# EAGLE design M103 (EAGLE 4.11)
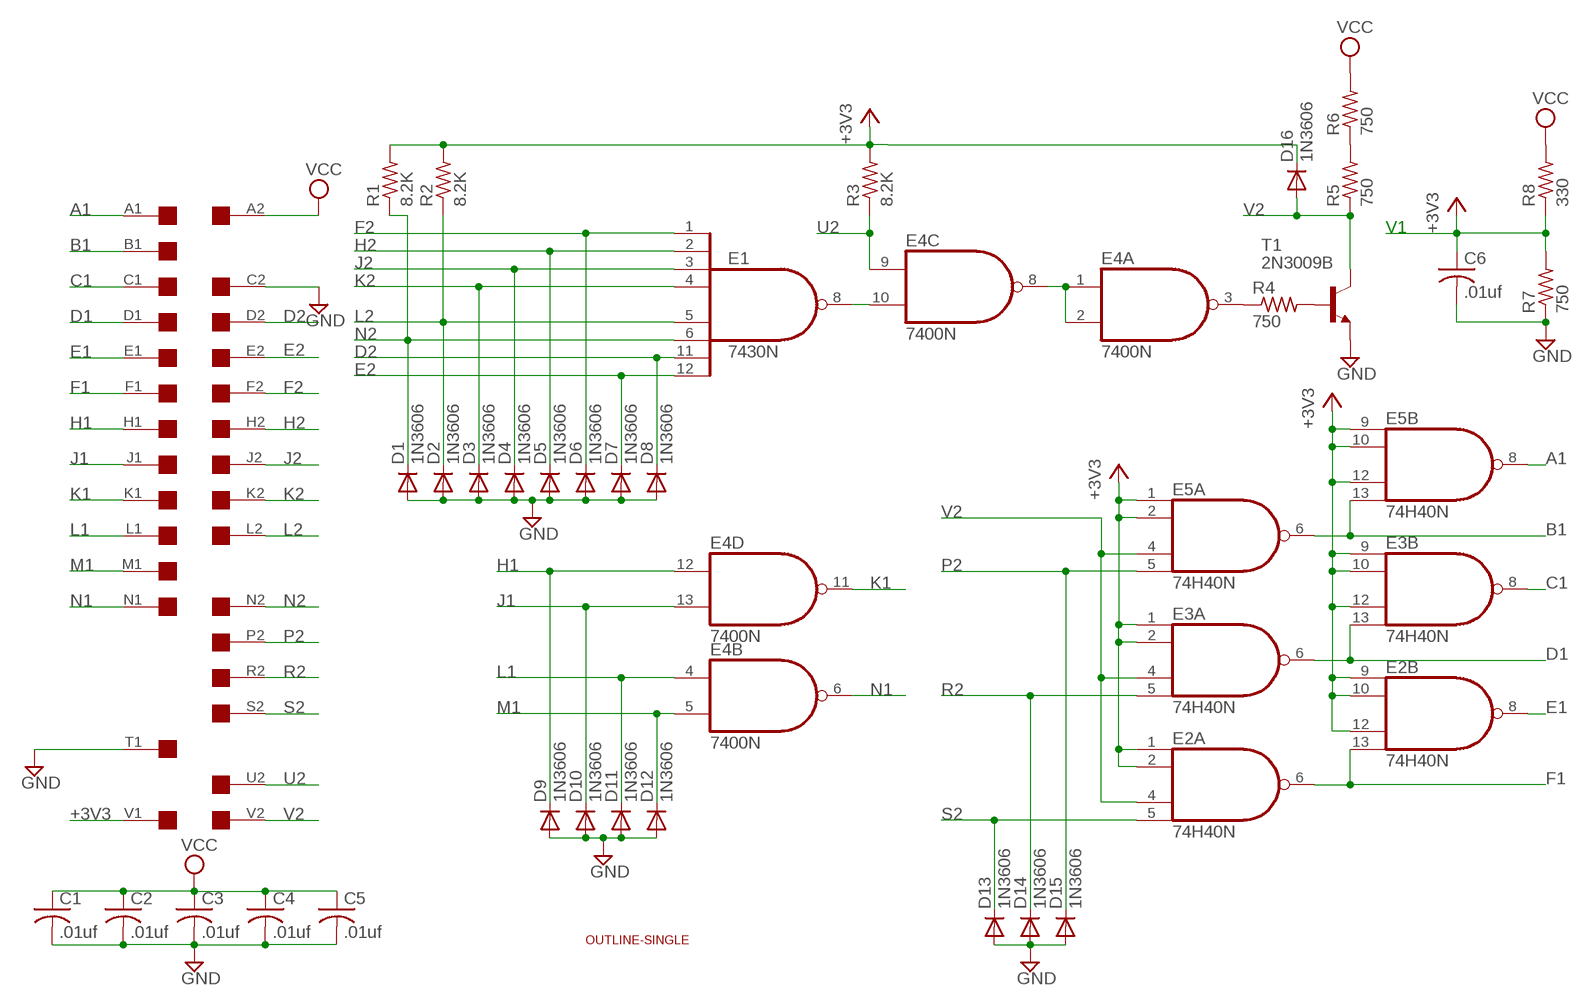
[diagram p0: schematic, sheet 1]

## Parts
C1  .01uf  C-US050-025X075  [C050-025X075]
C2  .01uf  C-US050-025X075  [C050-025X075]
C3  .01uf  C-US050-025X075  [C050-025X075]
C4  .01uf  C-US050-025X075  [C050-025X075]
C5  .01uf  C-US050-025X075  [C050-025X075]
C6  .01uf  C-US050-025X075  [C050-025X075]
D1  1N3606  1N4148  [DO35-10]
D2  1N3606  1N4148  [DO35-10]
D3  1N3606  1N4148  [DO35-10]
D4  1N3606  1N4148  [DO35-10]
D5  1N3606  1N4148  [DO35-10]
D6  1N3606  1N4148  [DO35-10]
D7  1N3606  1N4148  [DO35-10]
D8  1N3606  1N4148  [DO35-10]
D9  1N3606  1N4148  [DO35-10]
D10  1N3606  1N4148  [DO35-10]
D11  1N3606  1N4148  [DO35-10]
D12  1N3606  1N4148  [DO35-10]
D13  1N3606  1N4148  [DO35-10]
D14  1N3606  1N4148  [DO35-10]
D15  1N3606  1N4148  [DO35-10]
D16  1N3606  1N4148  [DO35-10]
E1  7430N  [DIL14]
E2  74H40N  74S20N  [DIL14]
E3  74H40N  74S20N  [DIL14]
E4  7400N  [DIL14]
E5  74H40N  74S20N  [DIL14]
R1  8.2K  R-US_0207/10  [0207/10]
R2  8.2K  R-US_0207/10  [0207/10]
R3  8.2K  R-US_0207/10  [0207/10]
R4  750  R-US_0207/10  [0207/10]
R5  750  R-US_0207/10  [0207/10]
R6  750  R-US_0207/10  [0207/10]
R7  750  R-US_0207/10  [0207/10]
R8  330  R-US_0207/10  [0207/10]
T1  2N3009B  2N1613-NPN-TO39-EBC  [TO39]
U$8  SINGLE  [EDGE-CON2]
U$9  OUTLINE-SINGLE  [SINGLE]

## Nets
+3V3: C6.1 D16.C E2.1(A:I0) E2.2(A:I1) E2.9(B:I0) E2.10(B:I1) E2.12(B:I2) E3.1(A:I0) E3.2(A:I1) E3.9(B:I0) E3.10(B:I1) E3.12(B:I2) E5.1(A:I0) E5.2(A:I1) E5.9(B:I0) E5.10(B:I1) E5.12(B:I2) R1.2 R2.2 R3.2 R7.2 R8.1 U$8.V1
A1: E5.8(B:O) U$8.A1
B1: E5.6(A:O) E5.13(B:I3) U$8.B1
C1: E3.8(B:O) U$8.C1
D1: E3.6(A:O) E3.13(B:I3) U$8.D1
D2: D8.C E1.11(I6) U$8.D2
E1: E2.8(B:O) U$8.E1
E2: D7.C E1.12(I7) U$8.E2
F1: E2.6(A:O) E2.13(B:I3) U$8.F1
F2: D6.C E1.1(I0) U$8.F2
GND: C1.2 C2.2 C3.2 C4.2 C5.2 C6.2 D1.A D2.A D3.A D4.A D5.A D6.A D7.A D8.A D9.A D10.A D11.A D12.A D13.A D14.A D15.A R7.1 T1.1(E) U$8.C2 U$8.T1
H1: D9.C E4.12(D:I0) U$8.H1
H2: D5.C E1.2(I1) U$8.H2
J1: D10.C E4.13(D:I1) U$8.J1
J2: D4.C E1.3(I2) U$8.J2
K1: E4.11(D:O) U$8.K1
K2: D3.C E1.4(I3) U$8.K2
L1: D11.C E4.4(B:I0) U$8.L1
L2: D2.C E1.5(I4) R2.1 U$8.L2
M1: D12.C E4.5(B:I1) U$8.M1
N1: E4.6(B:O) U$8.N1
N2: D1.C E1.6(I5) R1.1 U$8.N2
N$2: E4.3(A:O) R4.1
N$3: R4.2 T1.2(B)
N$5: R5.2 R6.1
N$8: E1.8(O) E4.10(C:I1)
N$9: E4.1(A:I0) E4.2(A:I1) E4.8(C:O)
P2: D15.C E5.5(A:I3) U$8.P2
R2: D14.C E3.5(A:I3) U$8.R2
S2: D13.C E2.5(A:I3) U$8.S2
U2: E4.9(C:I0) R3.1 U$8.U2
V2: D16.A E2.4(A:I2) E3.4(A:I2) E5.4(A:I2) R5.1 T1.3(C) U$8.V2
VCC: C1.1 C2.1 C3.1 C4.1 C5.1 R6.2 R8.2 U$8.A2
Unconnected: U$8.B2 U$8.M2 U$8.P1 U$8.R1 U$8.S1 U$8.T2 U$8.U1

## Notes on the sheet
- V1

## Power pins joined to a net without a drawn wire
GND: E1.7(GND) E2.7(P:GND) E3.7(P:GND) E4.7(P:GND) E5.7(P:GND)
VCC: E1.14(VCC) E2.14(P:VCC) E3.14(P:VCC) E4.14(P:VCC) E5.14(P:VCC)

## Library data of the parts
C1-C6 = rcl:C-US: CAPACITOR, American symbol
D1-D16 = diode:1N4148: DIODE
E1 = 74xx-us:74*30: 8-input NAND gate
E2 E3 E5 = 74xx-us:74*20: Dual 4-input NAND gate
E4 = 74xx-us:74*00: Quad 2-input NAND gate
R1-R8 = rcl:R-US_: RESISTOR, American symbol
T1 = transistor:*-NPN-: NPN Transistror
U$8 = dec-con:SINGLE: Single-Height DEC board
U$9 = dec-con:OUTLINE-*: Board outlines for DEC boards.

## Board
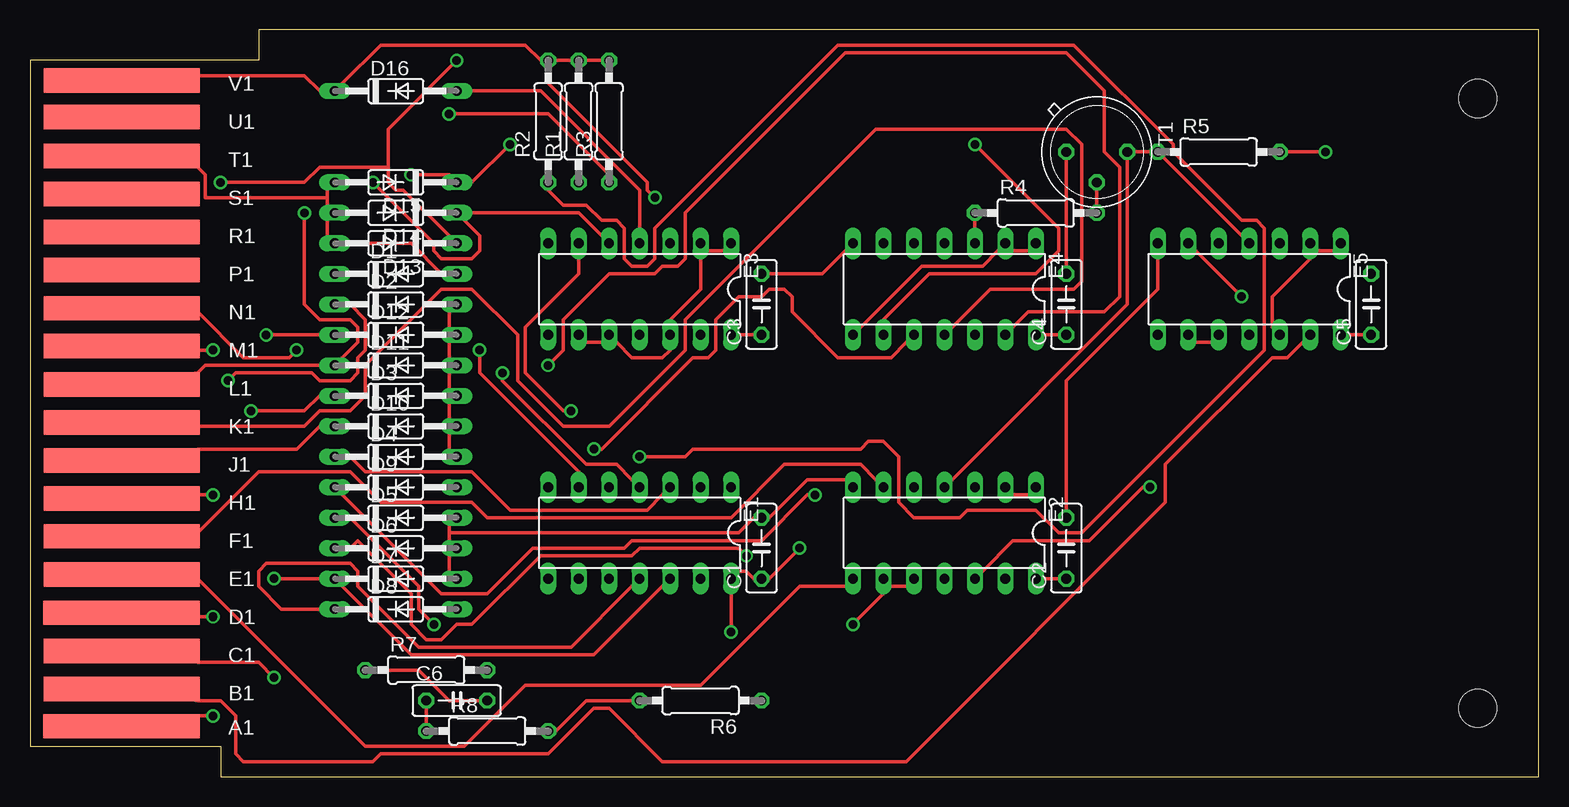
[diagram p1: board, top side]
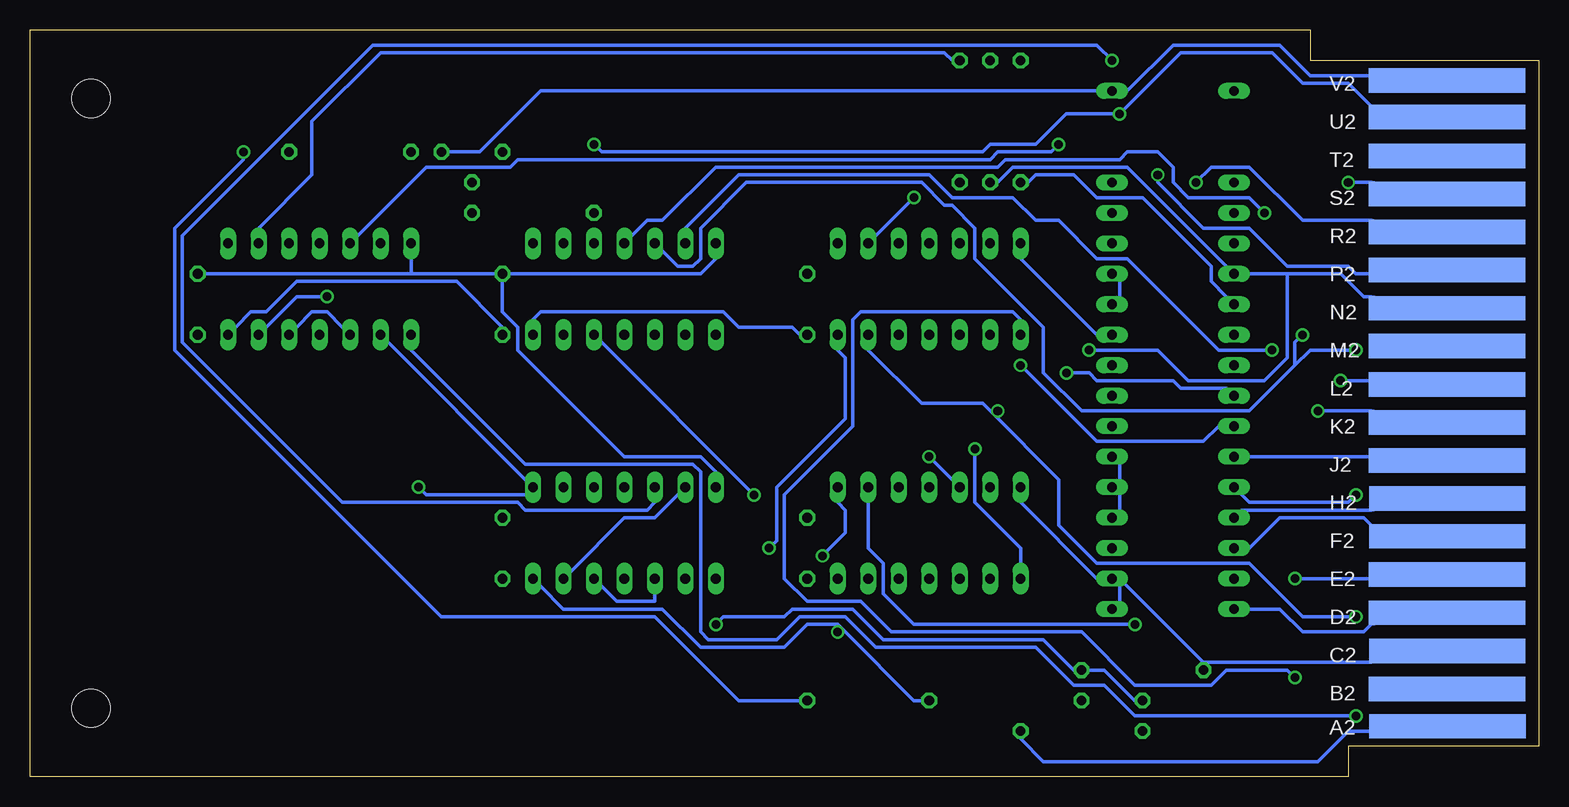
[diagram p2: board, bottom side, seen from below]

Size 125.73 x 62.23 mm. Coordinates in mm from the lower left corner, seen from the top.
Copper layers (1*16): Top 0.035mm / dielectric 1.5mm / Bottom 0.035mm
Design rules "10mils": minimum track width 12mil, minimum drill 28mil, track to track 10mil, track to pad 10mil, pad to pad 10mil, via to via 10mil, smd to smd 10mil, copper to edge 25mil, drill to drill 10mil, minimum pad ring 10mil, minimum via ring 8mil, stop-mask expansion 0mil, vias tented up to drill 0mil, thermal gap 10mil

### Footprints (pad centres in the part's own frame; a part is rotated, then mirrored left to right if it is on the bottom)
C050-025X075 = drill 0.813 octagon: 1 -2.54,0; 2 2.54,0
DO35-10 = drill 0.813 long: A 5.08,0; C -5.08,0
DIL14 = drill 0.813 long: 1 -7.62,-3.81; 2 -5.08,-3.81; 3 -2.54,-3.81; 4 0,-3.81; 5 2.54,-3.81; 6 5.08,-3.81; 7 7.62,-3.81; 8 7.62,3.81; 9 5.08,3.81; 10 2.54,3.81; 11 0,3.81; 12 -2.54,3.81; 13 -5.08,3.81; 14 -7.62,3.81
0207/10 = drill 0.813 octagon: 1 -5.08,0; 2 5.08,0
TO39 = drill 0.813 octagon: 1 0,-2.54; 2 2.54,0; 3 0,2.54
EDGE-CON2 = smd 13.017 x 2.032: A1 7.633,4.207; B1 7.639,7.327; C1 7.636,10.489; D1 7.633,13.665; E1 7.642,16.84; F1 7.642,20.041; H1 7.642,23.19; J1 7.642,26.34; K1 7.642,29.515; L1 7.642,32.69; M1 7.642,35.89; N1 7.642,39.04; P1 7.642,42.24; R1 7.642,45.39; S1 7.642,48.565; T1 7.642,51.74; U1 7.642,54.966; V1 7.642,58.026 | smd 13.017 x 2.032 bottom: A2 7.614,4.207; B2 7.642,7.328; C2 7.617,10.49; D2 7.642,13.665; E2 7.642,16.84; F2 7.617,20.041; H2 7.617,23.19; J2 7.642,26.34; K2 7.642,29.515; L2 7.642,32.69; M2 7.642,35.89; N2 7.642,39.04; P2 7.642,42.24; R2 7.642,45.39; S2 7.642,48.565; T2 7.642,51.74; U2 7.642,54.966; V2 7.642,58.026
SINGLE = hole 3.175: 120.65,56.515; 120.65,5.715

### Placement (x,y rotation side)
C1  60.96,19.05 90 top
C2  86.36,19.05 90 top
C3  60.96,39.37 90 top
C4  86.36,39.37 90 top
C5  111.76,39.37 90 top
C6  35.56,6.35 0 top
D1  30.48,41.91 0 top
D2  30.48,39.37 0 top
D3  30.48,31.75 0 top
D4  30.48,26.67 0 top
D5  30.48,21.59 0 top
D6  30.48,19.05 0 top
D7  30.48,16.51 0 top
D8  30.48,13.97 0 top
D9  30.48,24.13 0 top
D10  30.48,29.21 0 top
D11  30.48,34.29 0 top
D12  30.48,36.83 0 top
D13  30.48,44.45 180 top
D14  30.48,46.99 180 top
D15  30.48,49.53 180 top
D16  30.48,57.15 0 top
E1  50.8,20.32 180 top
E2  76.2,20.32 180 top
E3  50.8,40.64 180 top
E4  76.2,40.64 180 top
E5  101.6,40.64 180 top
R1  45.72,54.61 90 top
R2  43.18,54.61 90 top
R3  48.26,54.61 90 top
R4  83.82,46.99 0 top
R5  99.06,52.07 0 top
R6  55.88,6.35 180 top
R7  33.02,8.89 0 top
R8  38.1,3.81 0 top
T1  88.9,52.07 270 top
U$8  0,0 0 top
U$9  0,0 0 top

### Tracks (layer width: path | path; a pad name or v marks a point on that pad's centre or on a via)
+3V3  (via drill 0.71)
  Top 0.305: E3.9 46.36,36.2 47.63,36.2 E3.10 48.9,36.2 50.17,34.92 52.71,34.92 53.34,35.56 E3.12 53.34,38.1 55.88,40.64 55.88,43.18 E3.2 56.52,43.81 57.79,43.81 E3.1 | R2.2 43.82,59.69 45.09,59.69 R1.2 46.36,59.69 47.63,59.69 R3.2 | U$8.V1 13.97,58.42 22.86,58.42 24.13,57.15 D16.C 26.04,57.78 29.21,60.96 41.28,60.96 42.55,59.69 R2.2 | v52.07,48.26 51.44,48.9 51.44,49.53 43.18,57.78 43.18,59.05 R2.2 | R8.1 33.02,4.45 33.02,5.71 C6.1 | E2.10 73.03,15.88 71.76,15.88 E2.9 71.12,15.24 v68.58,12.7 | E5.1 108.59,43.81 107.32,43.81 E5.2 106.68,43.18 103.51,40.01 103.51,37.47 E5.12 | E2.2 81.92,23.5 83.19,23.5 E2.1 | E5.9 97.16,36.2 98.43,36.2 E5.10 | v93.35,24.13 92.71,24.13 88.27,19.68 81.92,19.68 79.38,17.14 E2.12
  Bottom 0.305: v52.07,48.26 55.25,45.09 E3.2 | C6.1 33.66,6.35 36.2,8.89 37.47,8.89 R7.2 38.74,8.89 41.28,11.43 54.61,11.43 57.15,13.97 62.23,13.97 62.87,13.34 67.95,13.34 v68.58,12.7 | E2.12 78.11,15.88 76.84,14.61 73.66,14.61 73.66,15.24 E2.10 | E5.12 103.51,37.47 102.24,38.73 100.97,38.73 99.7,37.47 E5.10 | E5.9 95.89,36.2 84.46,24.77 E2.1 84.46,23.5 92.71,23.5 v93.35,24.13 | R3.2 48.9,59.69 49.53,60.33 96.52,60.33 102.24,54.61 102.24,50.16 106.68,45.72 E5.2
A1  (via drill 0.71)
  Top 0.305: v15.24,5.08 13.97,5.08 U$8.A1
  Bottom 0.305: v15.24,5.08 33.66,5.08 36.2,7.62 38.74,7.62 41.91,10.79 55.25,10.79 57.79,13.34 61.6,13.34 63.5,11.43 69.22,11.43 69.85,12.06 69.85,25.4 70.49,26.04 84.46,26.04 93.98,35.56 E5.8
B1  (via drill 0.71)
  Top 0.305: v100.97,40.01 97.16,43.81 E5.6 | E5.13 106.05,36.2 104.78,34.92 103.51,34.92 94.62,26.04 94.62,22.86 73.03,1.27 52.71,1.27 48.26,5.71 46.99,5.71 43.18,1.91 29.21,1.91 28.58,1.27 17.78,1.27 17.15,1.91 17.15,5.08 15.88,6.35 13.97,6.35 U$8.B1
  Bottom 0.305: v100.97,40.01 103.51,40.01 106.05,37.47 E5.13
C1  (via drill 0.71)
  Top 0.305: v20.32,8.26 19.05,9.53 13.97,9.53 U$8.C1
  Bottom 0.305: v20.32,8.26 20.96,8.89 26.04,8.89 27.31,7.62 33.66,7.62 38.1,12.06 53.98,12.06 56.52,14.61 60.96,14.61 62.87,16.51 62.87,23.5 57.15,29.21 57.15,38.1 56.52,38.73 43.82,38.73 43.18,38.1 E3.8
D1  (via drill 0.71)
  Top 0.305: v15.24,13.34 13.97,13.34 U$8.D1 | v45.09,30.48 44.45,30.48 41.28,33.66 41.28,37.47 45.72,41.91 45.72,43.18 E3.6
  Bottom 0.305: v15.24,13.34 19.69,13.34 24.13,17.78 36.83,17.78 40.01,20.95 40.01,24.77 45.72,30.48 | 45.72,30.48 46.36,31.11 51.44,31.11 55.88,35.56 E3.13 | 45.72,30.48 v45.09,30.48
D2
  Top 0.305: E1.11 50.17,15.88 45.09,10.79 32.39,10.79 27.31,15.88 27.31,17.14 26.67,17.78 19.69,17.78 19.05,17.14 19.05,15.88 20.96,13.97 24.13,13.97 D8.C
  Bottom 0.305: D8.C 24.13,13.97 21.59,13.97 19.69,12.06 14.61,12.06 13.97,12.7 U$8.D2
E1
  Top 0.305: E2.8 67.95,15.88 64.14,15.88 55.88,7.62 41.28,7.62 36.2,2.54 27.94,2.54 13.97,16.51 U$8.E1
E2  (via drill 0.71)
  Top 0.305: v20.32,16.51 24.13,16.51 D7.C 26.04,15.88 31.75,10.16 46.99,10.16 52.71,15.88 E1.12
  Bottom 0.305: v20.32,16.51 13.97,16.51 U$8.E2
F1
  Top 0.305: E2.6 70.49,24.77 69.22,26.04 62.87,26.04 58.42,21.59 38.1,21.59 36.83,22.86 29.21,22.86 26.67,25.4 19.05,25.4 13.97,20.32 U$8.F1
  Bottom 0.305: E2.13 80.65,17.14 76.2,21.59 73.66,21.59 71.76,23.5 E2.6
F2  (via drill 0.71)
  Top 0.305: v59.69,18.41 59.06,19.05 50.8,19.05 50.17,18.41 42.55,18.41 36.83,12.7 35.56,12.7 34.29,11.43 33.02,11.43 31.75,12.7 31.75,15.24 27.31,19.68 26.67,19.05 D6.C
  Bottom 0.305: U$8.F2 13.97,20.95 14.61,21.59 21.59,21.59 24.13,19.05 D6.C | v59.69,18.41 57.79,20.32 57.79,22.23 58.42,22.86 E1.1
GND
  Top 0.305: C2.2 86.36,22.23 86.36,33.02 93.98,40.64 93.98,43.18 E5.7 | C3.2 61.6,41.91 66.04,41.91 67.95,43.81 E4.7 | C4.2 86.36,42.55 86.36,51.44 T1.1 | E2.7 67.95,24.77 64.77,24.77 61.6,21.59 C1.2 60.33,21.59 59.06,20.32 34.93,20.32 | 24.77,48.26 24.77,47.62 D14.A 24.77,46.35 24.77,45.09 D13.A 26.67,44.45 31.75,44.45 34.29,41.91 D1.A | 24.77,48.26 24.77,48.9 D15.A | D7.A 34.93,17.14 34.93,18.41 D6.A 34.93,19.68 34.93,20.32 | 34.93,20.32 34.93,20.95 D5.A | D4.A 34.93,27.3 34.93,28.57 D10.A 34.93,29.84 34.93,31.11 D3.A 34.93,32.38 34.93,33.66 D11.A 34.93,34.92 34.93,36.2 D12.A 34.93,37.47 34.93,38.73 D2.A | C6.2 37.47,6.35 34.93,6.35 32.39,8.89 28.58,8.89 R7.1 | 24.77,48.26 14.61,48.26 14.61,50.16 13.97,50.8 U$8.T1
  Bottom 0.305: 93.98,41.91 87,41.91 C4.2 | 93.98,41.91 111.13,41.91 C5.2 | E4.7 68.58,43.18 69.85,41.91 85.73,41.91 C4.2 | 93.98,41.91 93.98,43.18 E5.7 | 27.94,9.53 34.93,16.51 D7.A | 27.94,9.53 R7.1 27.94,9.53 | D8.A 34.93,14.61 34.93,15.88 D7.A | D5.A 34.93,22.23 34.93,23.5 D9.A 34.93,24.77 34.93,26.04 D4.A | D1.A 34.93,41.27 34.93,40.01 D2.A | E1.7 43.18,22.86 36.83,16.51 D7.A | E3.7 43.18,43.18 36.83,36.83 D12.A | 27.94,9.53 13.97,9.53 U$8.C2 | C4.2 86.36,41.27 86.36,38.73 85.09,37.47 85.09,35.56 76.2,26.67 69.85,26.67 68.58,25.4 E2.7
H1  (via drill 0.71)
  Top 0.305: v15.24,23.5 13.97,23.5 U$8.H1 | v65.41,23.5 64.77,23.5 60.96,19.68 50.17,19.68 49.53,19.05 41.91,19.05 38.1,15.24 34.29,15.24 26.04,23.5 D9.C
  Bottom 0.305: v15.24,23.5 15.88,22.86 24.13,22.86 24.77,23.5 D9.C | v65.41,23.5 78.11,36.2 E4.12
H2  (via drill 0.71)
  Top 0.305: v33.66,12.7 32.39,13.97 32.39,15.88 26.67,21.59 D5.C
  Bottom 0.305: U$8.H2 13.97,22.23 24.77,22.23 D5.C | v33.66,12.7 52.07,12.7 54.61,15.24 54.61,17.78 55.88,19.05 55.88,22.86 E1.2
J1  (via drill 0.71)
  Top 0.305: U$8.J1 13.97,27.3 22.23,27.3 24.13,29.21 D10.C | v43.18,34.29 44.45,35.56 44.45,38.1 48.26,41.91 52.07,41.91 52.71,42.55 53.98,42.55 54.61,43.18 54.61,46.99 67.95,60.33 86.36,60.33 89.54,57.15 89.54,52.07 90.81,50.8 90.81,40.01 89.54,38.73 83.19,38.73 81.92,37.47 E4.13
  Bottom 0.305: v43.18,34.29 36.83,27.94 27.94,27.94 26.67,29.21 D10.C
J2
  Top 0.305: E1.3 52.71,23.5 51.44,22.23 40.01,22.23 36.83,25.4 27.94,25.4 26.67,26.67 D4.C
  Bottom 0.305: D4.C 24.13,26.67 13.97,26.67 U$8.J2
K1
  Top 0.305: E4.11 76.84,37.47 80.01,40.64 87,40.64 87.63,41.27 87.63,52.7 86.36,53.98 70.49,53.98 54.61,38.1 54.61,35.56 48.26,29.21 44.45,29.21 40.64,33.02 40.64,36.83 36.83,40.64 34.29,40.64 27.94,34.29 27.94,31.75 26.67,30.48 24.13,30.48 22.86,29.21 13.97,29.21 U$8.K1
K2  (via drill 0.71)
  Top 0.305: v18.42,30.48 22.86,30.48 24.13,31.75 D3.C | v39.37,33.66 39.37,33.02 46.36,26.04 48.9,26.04 50.17,24.77 E1.4
  Bottom 0.305: v18.42,30.48 13.97,30.48 U$8.K2 | v39.37,33.66 37.47,33.66 36.83,33.02 30.48,33.02 29.85,32.38 26.04,32.38 D3.C
L1  (via drill 0.71)
  Top 0.305: U$8.L1 13.97,33.66 14.61,34.29 24.13,34.29 D11.C 26.04,34.92 27.31,36.2 27.31,37.47 26.67,38.1 24.13,38.1 22.86,39.37 v22.86,46.99
  Bottom 0.305: v22.86,46.99 24.13,48.26 29.21,48.26 30.48,49.53 30.48,50.8 31.75,52.07 34.29,52.07 34.93,51.44 44.45,51.44 45.09,50.8 68.58,50.8 73.03,46.35 74.3,46.35 75.57,45.09 E4.4
L2  (via drill 0.71)
  Top 0.305: v16.51,33.02 17.15,33.66 23.5,33.66 24.13,33.02 26.67,33.02 27.31,33.66 27.31,34.92 27.94,35.56 27.94,38.1 26.67,39.37 D2.C | v50.8,26.67 54.61,26.67 55.25,27.3 69.22,27.3 69.85,27.94 71.12,27.94 72.39,26.67 72.39,22.86 73.66,21.59 77.47,21.59 78.11,22.23 83.82,22.23 85.73,20.32 87.63,20.32 102.87,35.56 102.87,45.72 102.24,46.35 100.97,46.35 95.25,52.07 95.25,52.7 87,60.96 67.31,60.96 52.07,45.72 52.07,43.18 51.44,42.55 50.17,42.55 49.53,43.18 49.53,45.72 48.9,46.35 47.63,46.35 46.36,47.62 44.45,47.62 43.18,48.9 R2.1
  Bottom 0.305: v16.51,33.02 13.97,33.02 U$8.L2 | R2.1 42.55,49.53 41.91,50.16 38.74,50.16 36.83,48.26 33.02,48.26 27.31,42.55 27.31,41.27 26.04,40.01 D2.C | v50.8,26.67 48.9,24.77 E1.5
M1  (via drill 0.71)
  Top 0.305: v15.24,35.56 13.97,35.56 U$8.M1 | v19.69,36.83 24.13,36.83 D12.C
  Bottom 0.305: v15.24,35.56 19.05,35.56 20.32,34.29 | 20.32,34.29 24.13,30.48 38.1,30.48 41.28,33.66 41.28,37.47 46.99,43.18 46.99,45.72 48.9,47.62 49.53,47.62 51.44,49.53 66.04,49.53 69.85,45.72 69.85,43.18 70.49,42.55 71.76,42.55 73.03,43.81 E4.5 | v19.69,36.83 20.32,36.2 20.32,34.29
N1  (via drill 0.71)
  Top 0.305: v22.23,35.56 21.59,34.92 17.78,34.92 13.97,38.73 U$8.N1
  Bottom 0.305: v22.23,35.56 26.67,35.56 34.29,43.18 36.83,43.18 40.01,46.35 41.91,46.35 43.82,48.26 48.9,48.26 50.8,50.16 66.68,50.16 71.12,45.72 E4.6
N2  (via drill 0.71)
  Top 0.305: v37.47,35.56 37.47,33.66 45.72,25.4 E1.6
  Bottom 0.305: 20.96,41.91 24.13,41.91 D1.C 26.04,42.55 34.29,50.8 43.82,50.8 45.09,49.53 R1.1 | 20.96,41.91 16.51,41.91 14.61,40.01 13.97,40.01 U$8.N2 | v37.47,35.56 31.75,35.56 29.21,33.02 22.86,33.02 20.96,34.92 20.96,41.91
N$2
  Top 0.305: E4.3 78.74,45.72 78.74,46.35 R4.1
N$3
  Top 0.305: R4.2 88.9,47.62 88.9,48.9 T1.2
N$5  (via drill 0.71)
  Top 0.305: v107.95,52.07 104.78,52.07 R5.2
  Bottom 0.305: v107.95,52.07 107.95,51.44 113.67,45.72 113.67,35.56 91.44,13.34 73.66,13.34 66.68,6.35 61.6,6.35 R6.1
N$8  (via drill 0.71)
  Top 0.305: v46.99,27.3 47.63,27.3 55.25,34.92 56.52,34.92 57.15,35.56 57.15,38.1 59.06,40.01 60.96,40.01 61.6,40.64 62.87,40.64 63.5,40.01 63.5,38.73 67.31,34.92 71.76,34.92 73.03,36.2 E4.10
  Bottom 0.305: v46.99,27.3 46.99,22.86 43.18,19.05 43.18,17.78 E1.8
N$9
  Top 0.305: E4.8 69.22,37.47 74.3,42.55 79.38,42.55 80.65,43.81 E4.2 81.92,43.81 83.19,43.81 E4.1
P2  (via drill 0.71)
  Top 0.305: v40.01,52.7 36.83,49.53 D15.C 34.93,50.16 v31.75,50.16
  Bottom 0.305: v40.01,52.7 40.64,52.07 45.09,52.07 45.72,51.44 85.09,51.44 85.73,50.8 92.71,50.8 98.43,45.09 E5.5 | v31.75,50.16 31.75,49.53 27.94,45.72 24.13,45.72 20.96,42.55 15.88,42.55 15.24,41.91 13.97,41.91 U$8.P2
R2  (via drill 0.71)
  Top 0.305: v28.58,49.53 33.66,44.45 33.66,43.81 34.29,43.18 36.83,43.18 37.47,43.81 37.47,45.09 36.2,46.35 D14.C 36.83,46.99 45.72,46.99 47.63,45.09 E3.5
  Bottom 0.305: v28.58,49.53 27.31,50.8 24.13,50.8 19.69,46.35 13.97,46.35 U$8.R2
S2  (via drill 0.71)
  Top 0.305: 29.85,50.8 29.85,53.98 v35.56,59.69 | 29.85,50.8 29.85,49.53 30.48,48.9 31.12,48.9 34.93,45.09 D13.C | v15.88,49.53 22.86,49.53 24.13,50.8 29.85,50.8
  Bottom 0.305: v35.56,59.69 36.83,60.96 97.16,60.96 113.03,45.09 113.03,36.2 99.7,22.86 85.09,22.86 84.46,22.23 74.3,22.23 73.66,22.86 E2.5 | v15.88,49.53 13.97,49.53 U$8.S2
U2  (via drill 0.71)
  Top 0.305: v34.93,55.24 43.18,55.24 48.26,50.16 R3.1 | v78.74,52.7 85.73,45.72 85.73,43.81 83.82,41.91 74.93,41.91 71.12,38.1 E4.9
  Bottom 0.305: U$8.U2 13.97,55.88 15.88,57.78 19.69,57.78 22.23,60.33 29.85,60.33 v34.93,55.24 39.37,55.24 41.91,52.7 45.72,52.7 46.36,52.07 78.11,52.07 v78.74,52.7
V2
  Top 0.305: E2.4 76.84,24.77 91.44,39.37 91.44,51.44 T1.3 92.08,52.07 93.35,52.07 R5.1 100.97,45.09 E5.4 | D16.A 36.83,57.15 42.55,57.15 50.8,48.9 50.8,45.72 E3.4
  Bottom 0.305: U$8.V2 13.97,58.42 19.05,58.42 21.59,60.96 30.48,60.96 34.29,57.15 D16.A 36.83,57.15 83.19,57.15 88.27,52.07 90.81,52.07 T1.3
VCC  (via drill 0.71)
  Top 0.305: E5.14 109.86,36.83 111.13,36.83 C5.1 | E3.14 59.06,36.83 60.33,36.83 C3.1 | E4.14 84.46,36.83 85.73,36.83 C4.1 | E2.14 84.46,16.51 85.73,16.51 C2.1 | R6.2 50.17,6.35 46.36,6.35 43.82,3.81 R8.2 | v58.42,12.06 58.42,15.24 E1.14 59.06,17.14 59.69,17.14 60.33,16.51 C1.1 61.6,16.51 v64.14,19.05
  Bottom 0.305: C3.1 61.6,36.83 62.23,37.47 66.68,37.47 67.95,38.73 83.19,38.73 83.82,38.1 E4.14 | E5.14 108.59,37.47 107.32,38.73 106.05,38.73 103.51,41.27 90.17,41.27 86.36,37.47 C4.1 | U$8.A2 13.97,3.81 15.88,3.81 18.42,1.27 41.28,1.27 43.18,3.17 R8.2 | 57.79,12.06 v58.42,12.06 | 57.79,12.06 52.07,6.35 51.44,6.35 R6.2 | 57.79,12.06 58.42,12.7 60.96,12.7 62.87,10.79 69.85,10.79 73.03,13.97 81.28,13.97 83.19,15.88 E2.14 | v64.14,19.05 63.5,19.68 63.5,24.13 57.79,29.84 57.79,34.92 58.42,35.56 E3.14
